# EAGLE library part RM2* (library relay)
Power Relay SCHRACK 2 pole 16 A, DC- or AC-coil Source: http://www.schrack.com/.. 5829.pdf
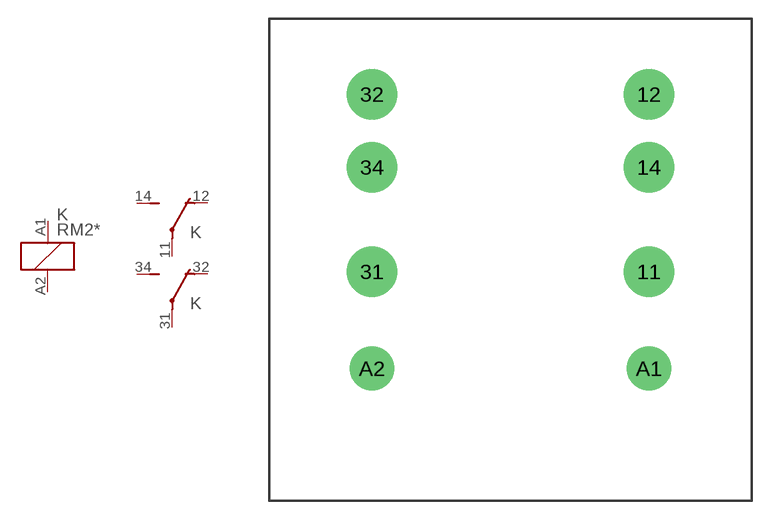
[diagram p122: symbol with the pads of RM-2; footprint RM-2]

Designator prefix K; gates 1=K 2=U 3=U

## RM2506 (OC_FARNELL: unknown; OC_NEWARK: unknown), RM2512 (OC_FARNELL: unknown; OC_NEWARK: unknown), RM2524 (OC_FARNELL: unknown; OC_NEWARK: unknown), RM2548 (OC_FARNELL: unknown; OC_NEWARK: unknown), RM2615 (OC_FARNELL: unknown; OC_NEWARK: unknown), RM2730 (OC_FARNELL: unknown; OC_NEWARK: unknown), RM2900 (OC_FARNELL: unknown; OC_NEWARK: unknown), RM2R06 (OC_FARNELL: unknown; OC_NEWARK: unknown), RM2R12 (OC_FARNELL: unknown; OC_NEWARK: unknown), RM2R24 (OC_FARNELL: unknown; OC_NEWARK: unknown), RM2R48 (OC_FARNELL: unknown; OC_NEWARK: unknown), RM2S15 (OC_FARNELL: unknown; OC_NEWARK: unknown), RM2T30 (OC_FARNELL: unknown; OC_NEWARK: unknown), RM2V00 (OC_FARNELL: unknown; OC_NEWARK: unknown)  [RM-2]
11  2:P  pas
12  2:O  pas
14  2:S  pas
31  3:P  pas
32  3:O  pas
34  3:S  pas
A1  1:1  pas
A2  1:2  pas

## Footprint RM-2 (pad centres in mm)
Power Relay SCHRACK 2 pole 16 A, DC- or AC-coil Source: http://www.schrack.com/.. 5829.pdf
drill 2 pad 4 round: 11 11,-0.95; 12 11,13.15; 14 11,7.35; 31 -11,-0.95; 32 -11,13.15; 34 -11,7.35
drill 2 pad 3.5 round: A1 11,-8.65; A2 -11,-8.65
